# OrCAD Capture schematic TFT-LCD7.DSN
size B; title: TFT-LCD7; rev: 1.0; company: nuvoTon Technology Corp.; note: LCD
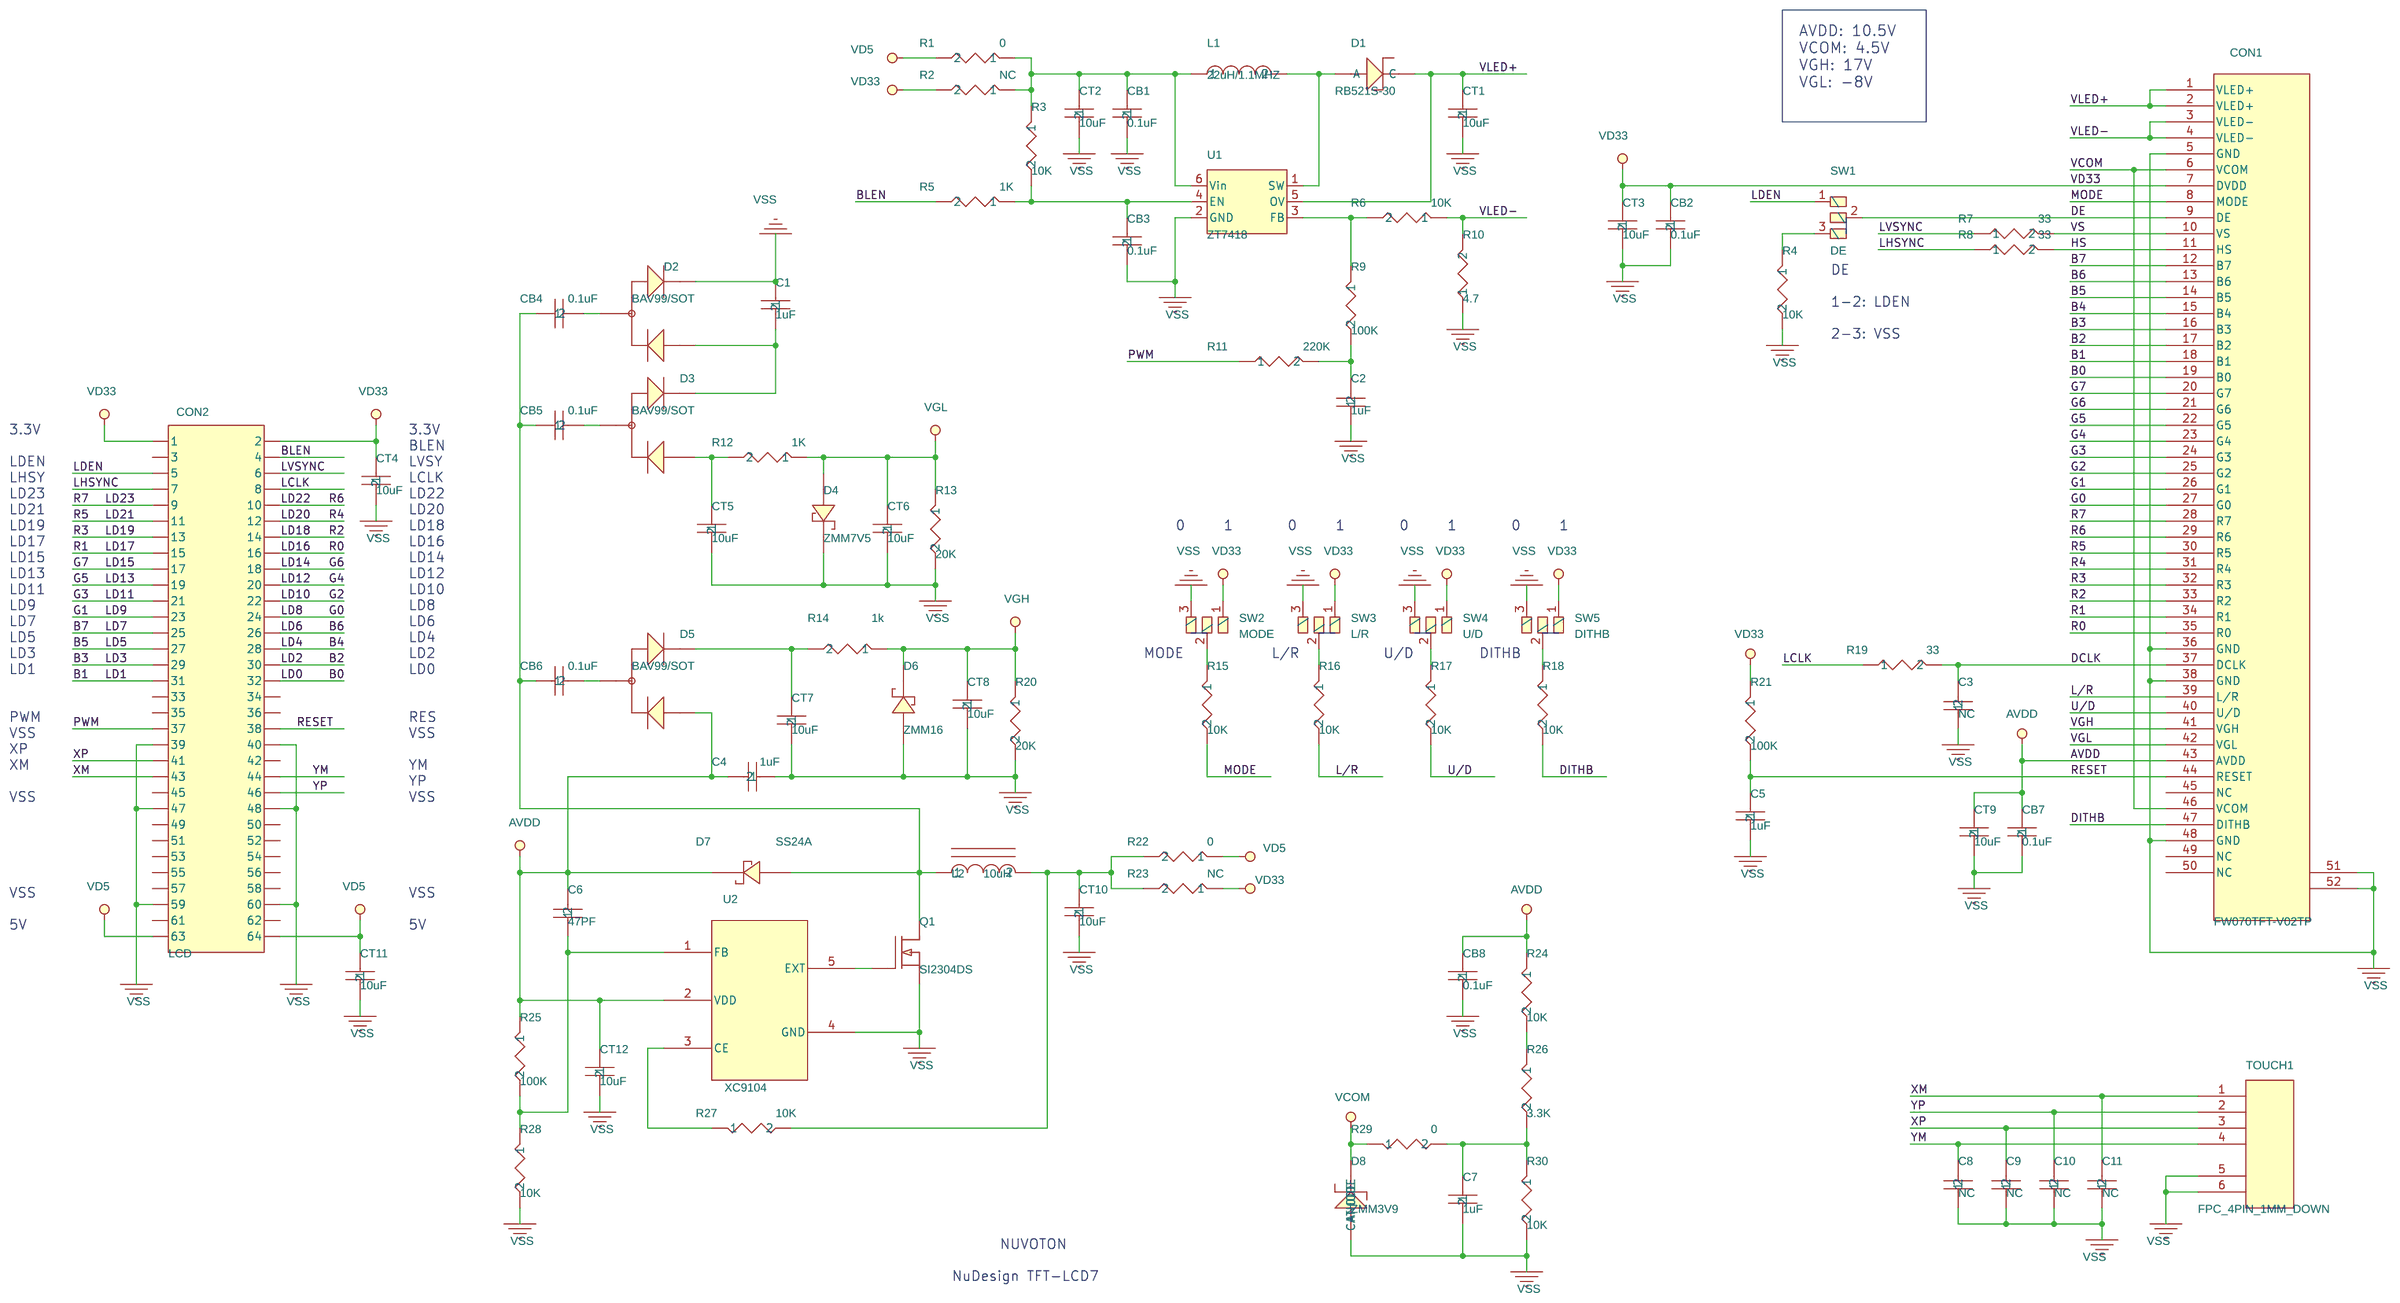
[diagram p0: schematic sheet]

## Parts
C1  1uF  [C0603]
C2  1uF  [C0603]
C3  NC  [C0603]
C4  1uF  [C0603]
C5  1uF  [C0603]
C6  47PF  [C0603]
C7  1uF  [C0603]
C8  NC  [C0603]
C9  NC  [C0603]
C10  NC  [C0603]
C11  NC  [C0603]
CB1  0.1uF  [C0603]
CB2  0.1uF  [C0603]
CB3  0.1uF  [C0603]
CB4  0.1uF  [C0603]
CB5  0.1uF  [C0603]
CB6  0.1uF  [C0603]
CB7  0.1uF  [C0603]
CB8  0.1uF  [C0603]
CON1  FW070TFT-V02TP  [FPC_50P_0.5MM]
CON2  LCD  [F_DIN_32X2/2.54A]
CT1  10uF  [C0603]
CT2  10uF  [C0603]
CT3  10uF  [C0603]
CT4  10uF  [C0603]
CT5  10uF  [C0603]
CT6  10uF  [C0603]
CT7  10uF  [C0603]
CT8  10uF  [C0603]
CT9  10uF  [C0603]
CT10  10uF  [C0603]
CT11  10uF  [C0603]
CT12  10uF  [C0603]
D1  RB521S-30  [Diode_A]
D2  BAV99/SOT  [SOT23]
D3  BAV99/SOT  [SOT23]
D4  ZMM7V5  [D1206]
D5  BAV99/SOT  [SOT23]
D6  ZMM16  [D1206]
D7  SS24A  [SOD123]
D8  ZMM3V9
L1  22uH/1.1MHZ  [L1008]
L2  10uH  [L1008]
Q1  SI2304DS  [SOT-23]
R1  0  [R0603]
R2  NC  [R0603]
R3  10K  [R0603]
R4  10K  [R0603]
R5  1K  [R0603]
R6  10K  [R0603]
R7  33  [R0603]
R8  33  [R0603]
R9  100K  [R0603]
R10  4.7  [R0603]
R11  220K  [R0603]
R12  1K  [R0603]
R13  20K  [R0603]
R14  1k  [R0603]
R15  10K  [R0603]
R16  10K  [R0603]
R17  10K  [R0603]
R18  10K  [R0603]
R19  33  [R0603]
R20  20K  [R0603]
R21  100K  [R0603]
R22  0  [R0603]
R23  NC  [R0603]
R24  10K  [R0603]
R25  100K  [R0603]
R26  3.3K  [R0603]
R27  10K  [R0603]
R28  10K  [R0603]
R29  0  [R0603]
R30  10K  [R0603]
SW1  DE  [3P-1.2mm]
SW2  MODE  [3P-1.2mm]
SW3  L/R  [3P-1.2mm]
SW4  U/D  [3P-1.2mm]
SW5  DITHB  [3P-1.2mm]
TOUCH1  FPC_4PIN_1MM_DOWN  [FPC_4PIN_1MM_C]
U1  ZT7418  [SOT23-6]
U2  XC9104  [SOT23-5]

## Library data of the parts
C1 = CAP_NP_8
C2 = CAP_NP_15
C3 = CAP_NP_21
C4 = CAP_NP
C5 = CAP-B_4: Package: C0402
C6 = CAP_NP_7
C7 = CAP-B_5: Package: C0402
C8 = CAP_NP_5
C9 = CAP_NP_9
C10 = CAP_NP_14
C11 = CAP_NP_1
CB1 = CAP-B_6: Package: C0402
CB2 = CAP_NP_6
CB3 = CAP-B_3: Package: C0402
CB4 = CAP-B: Package: C0402
CB5 = CAP-B_2: Package: C0402
CB6 = CAP-B_8: Package: C0402
CB7 = CAP_NP_4
CB8 = CAP-B_1: Package: C0402
CON1 = AT070TN94_0
CON2 = CON40A_0
CT1 = CAP-B_7: Package: C0402
CT2 = CAP_NP_13
CT3 = CAP_NP_12
CT4 = CAP_NP_16
CT5 = CAP_NP_10
CT6 = CAP_NP_20
CT7 = CAP_NP_3
CT8 = CAP_NP_19
CT9 = CAP_NP_11
CT10 = CAP_NP_18
CT11 = CAP_NP_2
CT12 = CAP_NP_17
D1 = ZENAR_0: Package: D
D2 D3 D5 = BAV99_SOT
D4 D6 D7 = ZHCS750_SOT_1
D8 = DIODE_ZENER
L1 = INDUCTOR: Package: L-3
L2 = INDUCTOR_IRON
Q1 = MOSFET_N_0
R1 = R_13: Package: R0402
R2 = R_8: Package: R0402
R3 = R_27: Package: R0402
R4 = R_26
R5 = R_1: Package: R0402
R6 = R_19: Package: R0402
R7 = R_25
R8 = R
R9 = R_16
R10 = R_9: Package: R0402
R11 = R_2
R12 = R_24
R13 = R_5
R14 = R_12
R15 = R_21
R16 = R_20
R17 = R_18
R18 = R_28
R19 = R_15
R20 = R_17
R21 = R_3
R22 = R_7: Package: R0402
R23 = R_14: Package: R0402
R24 = R_6
R25 = R_29
R26 = R_23
R27 = R_11
R28 = R_10
R29 = R_22
R30 = R_4
SW1-SW5 = SW-3PAD2
TOUCH1 = HEADER1X7_0
U1 = PJ9293
U2 = XC9104

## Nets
AVDD: C4.2 C6.2 CB7.1 CB8.1 CON1.43(AVDD) CT9.1 CT12.1 D5.1 D7.2(CATHODE) R24.1 R25.1 U2.2(VDD)
VSS: C1.1 C2.1 C3.1 C4.1 C5.2 C7.2 C8.1 C9.1 C10.1 C11.1 CB1.2 CB2.2 CB3.2 CB7.2 CB8.2 CON1.5(GND) CON1.36(GND) CON1.38(GND) CON1.48(GND) CON1.51 CON1.52 CON2.39 CON2.40 CON2.47 CON2.48 CON2.59 CON2.60 CT1.2 CT2.2 CT3.2 CT4.2 CT5.2 CT6.2 CT7.2 CT8.2 CT9.2 CT10.2 CT11.2 CT12.2 D2.2 D4.2(CATHODE) D6.1(ANODE) D8.ANODE Q1.2(SOURCE) R4.2 R10.1 R13.2 R20.2 R28.2 R30.2 SW2.3(\) SW3.3(\) SW4.3(\) SW5.3(\) TOUCH1.5 TOUCH1.6 U1.2(GND) U2.4(GND)
B0: CON1.19(B0) CON2.32
B1: CON1.18(B1) CON2.31
B2: CON1.17(B2) CON2.30
B3: CON1.16(B3) CON2.29
B4: CON1.15(B4) CON2.28
B5: CON1.14(B5) CON2.27
B6: CON1.13(B6) CON2.26
B7: CON1.12(B7) CON2.25
BLEN: CON2.4 R5.2
DCLK: C3.2 CON1.37(DCLK) R19.2
DE: CON1.9(DE) SW1.2(\)
DITHB: CON1.47(DITHB) R18.2
G0: CON1.27(G0) CON2.24
G1: CON1.26(G1) CON2.23
G2: CON1.25(G2) CON2.22
G3: CON1.24(G3) CON2.21
G4: CON1.23(G4) CON2.20
G5: CON1.22(G5) CON2.19
G6: CON1.21(G6) CON2.18
G7: CON1.20(G7) CON2.17
HS: CON1.11(HS) R8.2
L/R: CON1.39(L/R) R16.2
LCLK: CON2.8 R19.1
LD16: CON1.35(R0) CON2.16
LD17: CON1.34(R1) CON2.15
LD18: CON1.33(R2) CON2.14
LD19: CON1.32(R3) CON2.13
LD20: CON1.31(R4) CON2.12
LD21: CON1.30(R5) CON2.11
LD22: CON1.29(R6) CON2.10
LD23: CON1.28(R7) CON2.9
LDEN: CON2.5 SW1.1(\)
LHSYNC: CON2.7 R8.1
LVSYNC: CON2.6 R7.1
MODE: CON1.8(MODE) R15.2
PWM: CON2.37 R11.1
RESET: C5.1 CON1.44(RESET) CON2.38 R21.2
U/D: CON1.40(U/D) R17.2
VCOM: CON1.6(VCOM) CON1.46(VCOM) D8.CATHODE R29.1
VD5: CON2.63 CON2.64 CT11.1 R1.2 R22.1
VD33: CB2.1 CON1.7(DVDD) CON2.1 CON2.2 CT3.1 CT4.1 R2.2 R21.1 R23.1 SW2.1(\) SW3.1(\) SW4.1(\) SW5.1(\)
VGH: CON1.41(VGH) CT8.1 D6.2(CATHODE) R14.1 R20.1
VGL: CON1.42(VGL) CT6.1 D4.1(ANODE) R12.1 R13.1
VLED+: CON1.1(VLED+) CON1.2(VLED+) CT1.1 D1.2(C) U1.5(OV)
VLED-: CON1.3(VLED-) CON1.4(VLED-) R6.1 R10.2
VS: CON1.10(VS) R7.2
XM: C11.2 CON2.43 TOUCH1.1
XP: C9.2 CON2.41 TOUCH1.3
YM: C8.2 CON2.44 TOUCH1.4
YP: C10.2 CON2.46 TOUCH1.2
N16778568: CB1.1 CT2.1 L1.1 R1.1 R2.1 R3.1 U1.6(Vin)
N16778570: CB3.1 R3.2 R5.1 U1.4(EN)
N16778631: R6.2 R9.1 U1.3(FB)
N16778656: D1.1(A) L1.2 U1.1(SW)
N16778768: C2.2 R9.2 R11.2
N16783904: Q1.1(GATE) U2.5(EXT)
N16783920: CB4.1 CB5.1 CB6.1 D7.1(ANODE) L2.1 Q1.3(DRAIN)
N16783950: C6.1 R25.2 R28.1 U2.1(FB)
N16784013: R27.1 U2.3(CE)
N16784023: CT10.1 L2.2 R22.2 R23.2 R27.2
N16784102: CB5.2 D3.3
N16784104: CB4.2 D2.3
N16784139: CT7.1 D5.2 R14.2
N16784231: CT5.1 D3.1 R12.2
N16784321: C1.2 D2.1 D3.2
N16788092: CB6.2 D5.3
N16795691: C7.1 R26.2 R29.2 R30.1
N16795693: R24.2 R26.1
N16801242: R15.1 SW2.2(\)
N16801755: R16.1 SW3.2(\)
N16802295: R18.1 SW5.2(\)
N16802333: R17.1 SW4.2(\)
N16809385: R4.1 SW1.3(\)

Not connected (* = marked no-connect by the designer): CON1 45(NC) 49(NC) 50(NC); CON2 3 33 34 35 36 42 45 49 50 51 52 53 54 55 56 57 58 61 62

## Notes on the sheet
- AVDD: 10.5V
  VCOM: 4.5V
  VGH: 17V
  VGL: -8V
- DE
- 1-2: LDEN
- 2-3: VSS
- 3.3V
- 3.3V
- BLEN
- LDEN
- LVSY
- LD23
- LHSY
- LCLK
- LD22
- LD21
- LD20
- LD19
- LD18
- 0
- 1
- 0
- 1
- 0
- 1
- 0
- 1
- LD17
- LD16
- LD15
- LD14
- LD13
- LD12
- LD11
- LD9
- LD10
- LD8
- LD7
- LD6
- LD5
- LD4
- LD3
- LD2
- MODE
- L/R
- U/D
- DITHB
- LD1
- LD0
- PWM
- RES
- VSS
- VSS
- XP
- XM
- YM
- YP
- VSS
- VSS
- VSS
- VSS
- 5V
- 5V
- NUVOTON
- NuDesign TFT-LCD7
